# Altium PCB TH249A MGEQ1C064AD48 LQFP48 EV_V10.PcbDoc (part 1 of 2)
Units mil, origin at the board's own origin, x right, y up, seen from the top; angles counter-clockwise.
Board outline 3818.9 x 2637.8 mil, 2 copper layers (Top Layer, Bottom Layer); 103 components, 120 nets, 468 pads, 229 vias.
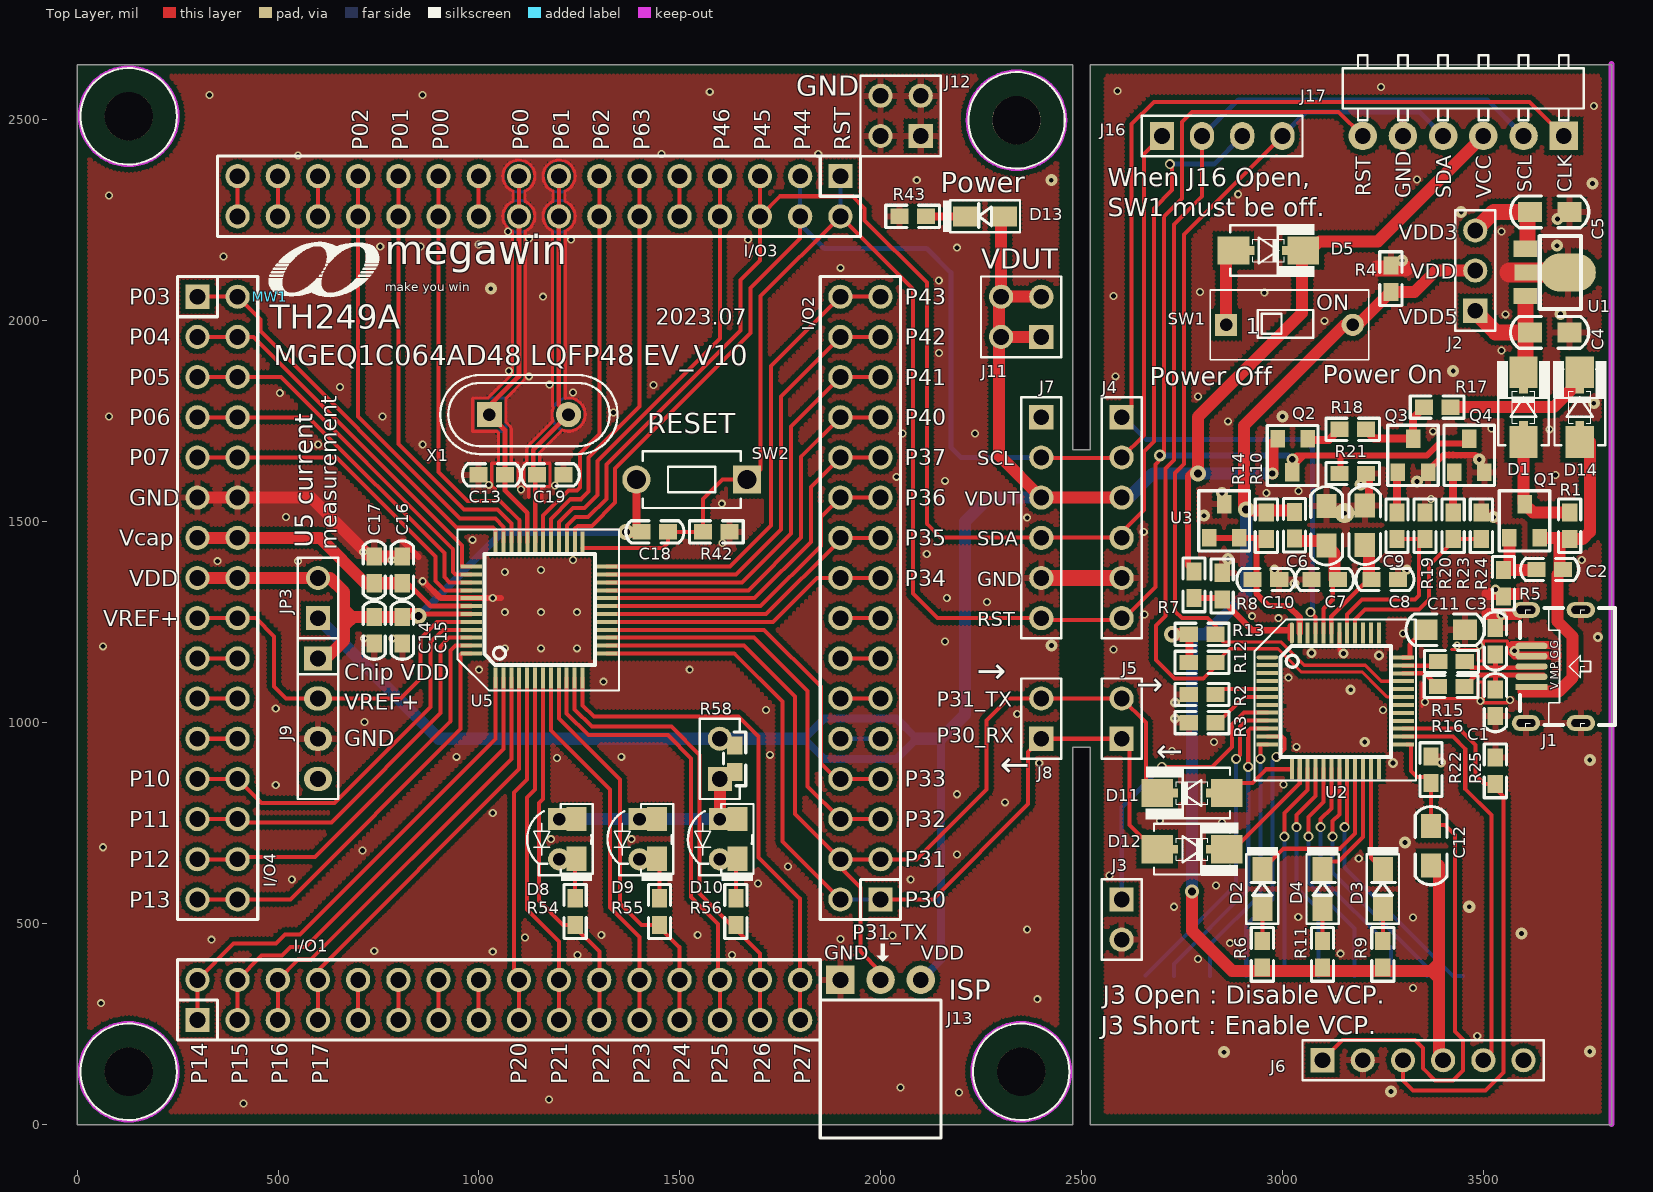
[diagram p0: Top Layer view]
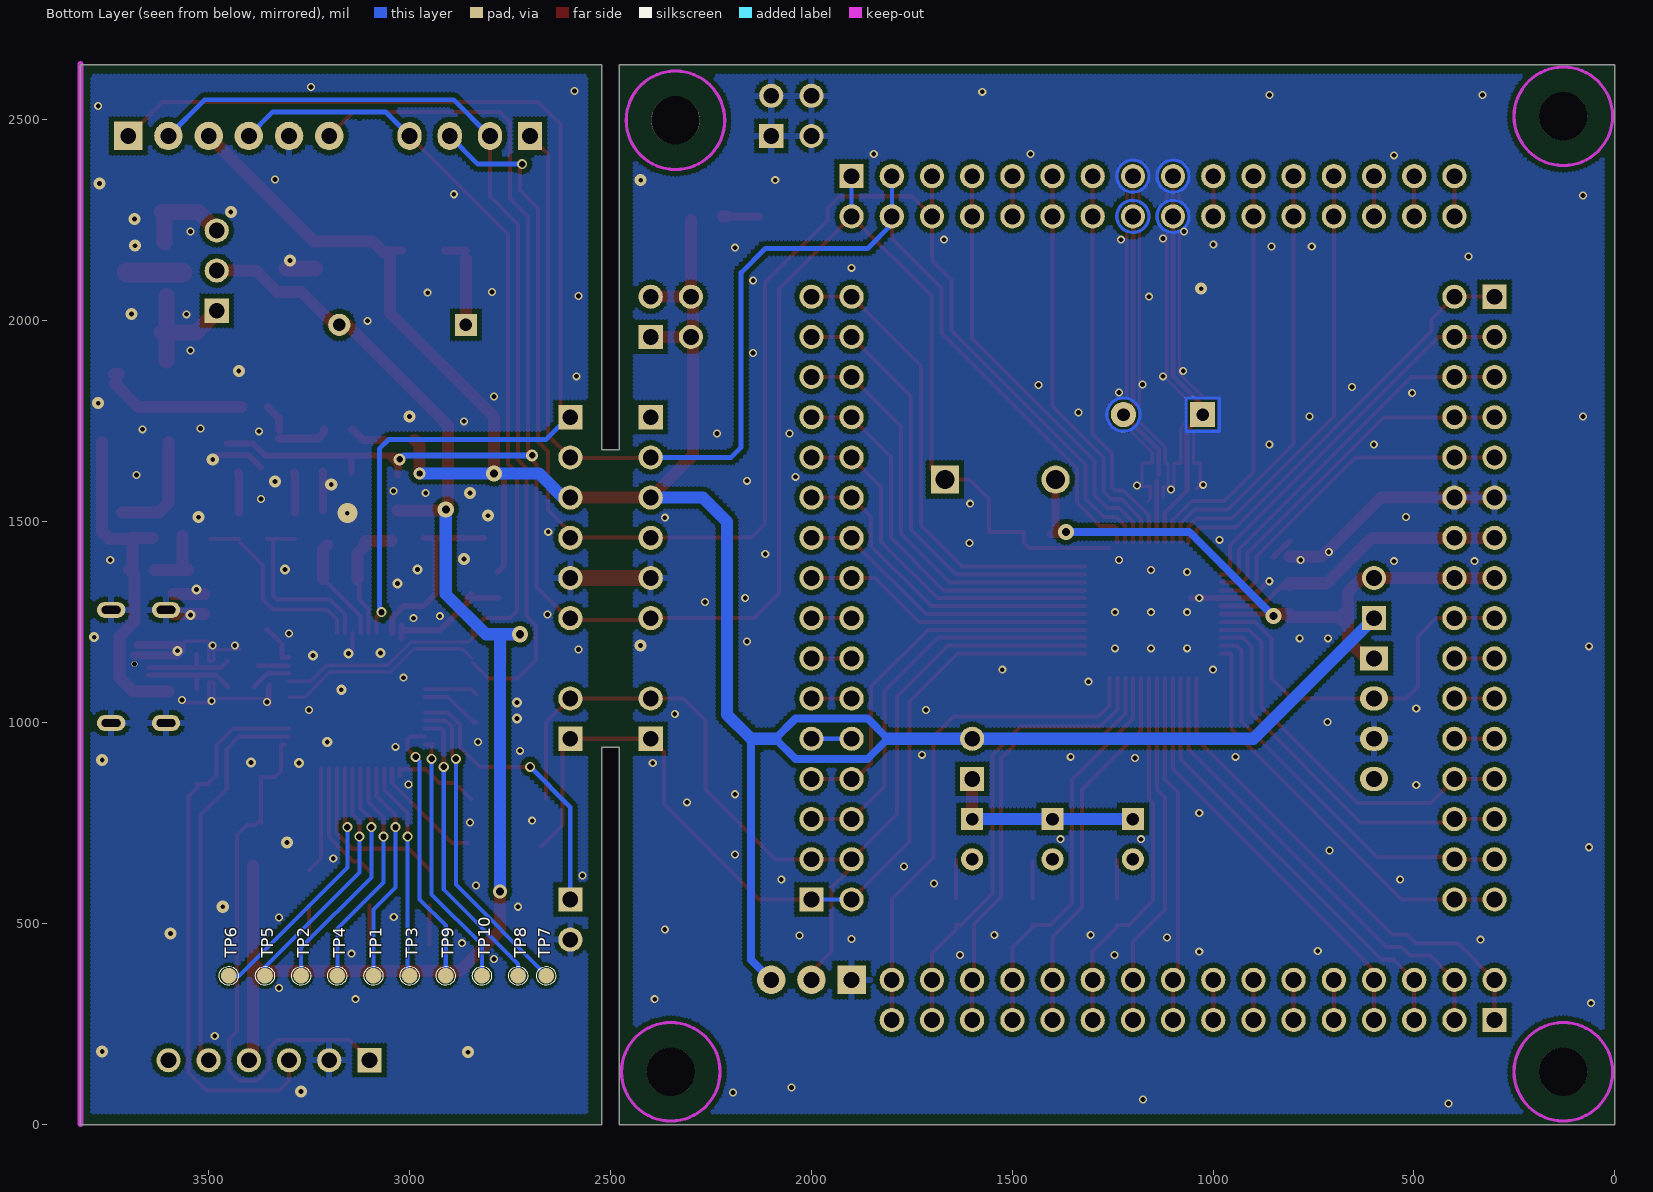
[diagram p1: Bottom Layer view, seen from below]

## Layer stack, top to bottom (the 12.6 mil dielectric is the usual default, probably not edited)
Top Layer: signal copper 1.4
Dielectric: dielectric 12.6, FR-4, Dk 4.8
Bottom Layer: signal copper 1.4

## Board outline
0,0 0,2637.8 2477.8,2637.8 2477.8,1678.74 2521.1,1678.74 2521.1,2637.8 3818.9,2637.8 3818.9,0 2521.1,0 2521.1,938.74 2477.8,938.74 2477.8,0

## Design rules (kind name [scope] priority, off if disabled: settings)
Clearance 12 [All] p1 off: gap=12
Clearance 7 [All] p2 off: gap=7
Clearance 6 [All] p3: gap=6
HoleSize 500-HoleSize [All] p1: absolutevalues=TRUE maxlimit=1500 minlimit=1 maxpercent=80.000 minpercent=20.000
PolygonConnect VIA [ISVIA] p1: connectstyle=Direct reliefconductorwidth=10 reliefentries=4 polygonreliefangle="90 Angle"
PolygonConnect "15 PolygonConnect" [All] p2: connectstyle=Relief reliefconductorwidth=15 reliefentries=4 polygonreliefangle="90 Angle"
RoomDefinition "2_MGEQ1C064AD48_LQFP48 EV_V10" [InComponentClass('2_MGEQ1C064AD48_LQFP48 EV_V10')] p1: confinementstyle=ConfineIn formatcopy=TRUE lockcomponents=FALSE outline -205.55,-40 3859.45,-40 3859.45,2680 -205.55,2680
RoomDefinition 1_MLink_V11 [InComponentClass('1_MLink_V11')] p2: confinementstyle=ConfineIn formatcopy=TRUE lockcomponents=FALSE outline -130.55,-90 3844.45,-90 3844.45,2735 -130.55,2735
RoutingVias [All] p1: holewidth=16 width=28 viastyle="Through Hole" minholewidth=16 minwidth=25 maxholewidth=28 maxwidth=50
ShortCircuit [All] p1 off: allowed=FALSE
SilkscreenOverComponentPads [All] p1: minsilkscreentomaskgap=10
SolderMaskExpansion [All] p1: expansion=4
UnRoutedNet [All] p1 off:
Width [All] p1: maxlimit=100 minlimit=6 preferedwidth=10
24 further rules are at their usual default settings.

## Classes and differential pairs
component class 1_MLink_V11: C1 C2 C3 C4 C5 C6 C7 C8 C9 C10 C11 C12 D1 D2 D3 D4 D5 D11 D12 D14 J1 J2 J3 J4 J5 J6 J16 J17 MW1 Q1 Q2 Q3 Q4 R1 R2 R3 R4 R5 R6 R7 R8 R9 R10 R11 R12 R13 R14 R15 R16 R17 R18 R19 R20 R21 R22 R23 R24 R25 SW1 TP1 TP2 TP3 TP4 TP5 TP6 TP7 TP8 TP9 TP10 U1 U2 U3
component class "2_MGEQ1C064AD48_LQFP48 EV_V10": C13 C14 C15 C16 C17 C18 C19 D8 D9 D10 D13 I/O1 I/O2 I/O3 I/O4 J7 J8 J9 J11 J12 J13 JP3 JP4 R42 R43 R54 R55 R56 R58 SW2 U5 X1

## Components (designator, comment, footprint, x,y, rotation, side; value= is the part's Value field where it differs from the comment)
C1 "15pF" 0603C#1 3529.45,1050 r90 top
C2 "0.1uF" 0603C#1 3664.41,1381.26 r0 top
C3 "15pF" 0603C#1 3529.45,1203 r270 top
C4 "4.7uF" 0805C 3664.41,1971.26 r0 top
C5 "4.7uF" 0805C 3664.41,2271.26 r0 top
C6 "4.7uF" 0805C 3109.41,1490 r90 top
C7 "0.1uF" 0603C#1 3104.45,1356.26 r180 top
C8 "0.1uF" 0603C#1 3254.45,1356.26 r0 top
C9 "4.7uF" 0805C 3204.41,1491.26 r90 top
C10 "0.1uF" 0603C#1 2958.5,1356.26 r180 top
C11 "4.7uF" 0805C 3404.41,1231.26 r0 top
C12 "4.7uF" 0805C 3369.45,694 r90 top
C13 "NC" 0603C#1 1031.49,1616.68 r0 top (schematic designator C18)
C14 "10uF" 0603C#2 739.45,1230 r270 top
C15 "0.1uF" 0603C#2 809.45,1230 r270 top
C16 "0.1uF" 0603C#2 809.45,1380 r90 top
C17 "4.7uF" 0603C#2 739.45,1380 r90 top
C18 "4.7uF" 0603C#2 1437.93,1475 r0 top (schematic designator C13)
C19 "NC" 0603C#1 1177.49,1616.68 r180 top
D1 "1N5817" DIODE_SMA_SOD323 3599.41,1785 r90 top
D2 "Yellow" 0805D 2949.45,586.26 r90 top
D3 "Green" 0805D 3249.45,586.26 r90 top
D4 "Red" 0805D 3099.45,586.26 r90 top
D5 "1N5817" DIODE_SMA_SOD323 2964.41,2175 r0 top
D8 "Red" LED38+0805 1199.45,710 r270 top
D9 "Yellow" LED38+0805 1399.45,710 r270 top
D10 "Green" LED38+0805 1599.45,710 r270 top
D11 "1N5817" DIODE_SMA_SOD323 2774.45,825 r180 top
D12 "1N5817" DIODE_SMA_SOD323 2774.45,685 r0 top
D13 "Yellow" 0805D 2259.45,2260 r180 top
D14 "1N5817" DIODE_SMA_SOD323 3739.41,1785 r90 top
I/O1 "CON16X2" PS16X2P254 299.45,260 r0 top locked
I/O2 "CON16X2" PS16X2P254 1999.45,560 r90 top locked
I/O3 "CON16X2" PS16X2P254 1899.45,2360 r180 top locked
I/O4 "CON16X2" PS16X2P254 299.45,2060 r270 top locked
J1 "MICRO_USB" USB_MICRO_7.X6P065 3742.21,1139.85 r90 top
J2 "2&3 (0 ohm)" PS3P254 3479.45,2025 r90 top
J3 "VCP Option" PS2P254 2599.45,560 r270 top locked
J4 "OnBoard ICP/SWD Connector" PS6P254 2599.45,1760 r270 top locked
J5 "NC" PS2P254 2599.45,960 r90 top locked
J6 "CON6" PS6P254 3099.45,160 r0 top locked
J7 "CON6" PS6P254 2399.45,1760 r270 top locked
J8 "NC" PS2P254 2399.45,960 r90 top
J9 "" PS4P254 599.45,1160 r270 top
J11 "VDUT" PS2X2P254 2399.45,1960 r90 top
J12 "GND" PS2X2P254 2099.45,2460 r90 top
J13 "3P2.54_F_90" PS3P254f_90 1899.45,360 r0 top
J16 "When J16 Open, SW1 must be off." PS4P254 2699.45,2460 r0 top locked
J17 "Off Board ICP/SWD Connector" PS6P254_90 3699.45,2460 r180 top locked
JP3 "JUMPER_2" ps2p254 599.45,1260 r90 top
MW1 "MW-A4" MEGAWIN_3.4 479.45,2060 r0 top
Q1 "IRLML6402" SOT23 3601.95,1501.97 r0 top
Q2 "2N3906" SOT23 3024.91,1665 r180 top
Q3 "3904" SOT23_132 3324.45,1665 r0 top
Q4 "3904" SOT23_132 3464.45,1665 r0 top
R1 "NC" 0603R 3714.45,1490 r270 top
R2 "0" 0603R 2799.45,1070 r0 top
R3 "NC" 0603R 2799.45,1000 r0 top
R4 "3.3K" 0603R 3269.45,2105 r270 top
R5 "1M" 0603R 3549.45,1347 r270 top
R6 "1K" 0603R 2949.45,423.26 r270 top
R7 "30K" 0603R 2779.45,1343 r90 top
R8 "10K" 0603R 2849.45,1340 r270 top
R9 "1K" 0603R 3249.45,423.26 r270 top
R10 "10" 0603R 3029.41,1491.26 r90 top
R11 "1K" 0603R 3099.45,423.26 r270 top
R12 "1.5K" 0603R 2799.45,1150 r180 top
R13 "1.5K" 0603R 2799.45,1220 r180 top
R14 "1K" 0603R 2959.41,1490 r270 top
R15 "30" 0603R 3420.29,1152.31 r180 top
R16 "30" 0603R 3419.45,1090 r180 top
R17 "4.7K" 0603R 3384.41,1785 r0 top
R18 "1K" 0603R 3174.45,1730 r0 top
R19 "4.7K" 0603R 3284.45,1490 r270 top
R20 "10K" 0603R 3354.45,1490 r270 top
R21 "1M" 0603R 3174.45,1620 r180 top
R22 "47K" 0603R 3369.45,883 r90 top
R23 "4.7K" 0603R 3424.45,1490 r270 top
R24 "10K" 0603R 3494.45,1490 r270 top
R25 "47K" 0603R 3529.45,880 r270 top
R42 "47K" 0603R 1590.93,1475 r180 top (schematic designator R27)
R43 "1K" 0603R 2079.45,2260 r180 top
R54 "470" 0603R 1239.45,530 r270 top
R55 "470" 0603R 1449.45,530 r270 top
R56 "470" 0603R 1639.45,530 r270 top
R58 "0" PS2p254+0603 1599.45,860 r90 top
SW1 "SW KEY-SPST" DIP2_SW 2859.49,1990 r0 top
SW2 "SW TACT-SPST" SW_T_2P 1529.45,1605 r180 top
TP1 "T POINT A" PIN1_1H0 3089.45,370 r90 bottom
TP2 "T POINT A" PIN1_1H0 3269.45,370 r90 bottom
TP3 "T POINT A" PIN1_1H0 2999.45,370 r180 bottom
TP4 "T POINT A" PIN1_1H0 3179.45,370 r180 bottom
TP5 "T POINT A" PIN1_1H0 3359.45,370 r180 bottom
TP6 "T POINT A" PIN1_1H0 3449.45,370 r180 bottom
TP7 "T POINT A" PIN1_1H0 2659.45,370 r180 bottom
TP8 "T POINT A" PIN1_1H0 2729.45,370 r180 bottom
TP9 "T POINT A" PIN1_1H0 2909.45,370 r180 bottom
TP10 "T POINT A" PIN1_1H0 2819.45,370 r90 bottom
U1 "AIC1734-33(SOT-89)" SOT89 3604.41,2120.31 r270 top
U2 "MG84FG516_LQFP48" LQFP48_7X7_050#1 3130.92,1054.39 r270 top
U3 "TL431A" SOT23 2854.41,1501.97 r0 top
U5 "MGEQ1C064AD48_LQFP48" LQFP48_7X7_050#2 1149.45,1280 r0 top locked
X1 "NC" X49U 1124.49,1766.68 r0 top

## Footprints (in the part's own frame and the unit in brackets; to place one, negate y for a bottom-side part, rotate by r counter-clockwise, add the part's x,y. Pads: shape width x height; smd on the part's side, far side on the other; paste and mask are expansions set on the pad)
0603C#1 [mil]
  rect 45x38 smd: 1(33,0) 2(-33,0)
  silkscreen extent -72,-28 72,28
0603C#2 [mil]
  rect 45x38 smd: 1(-33,0) 2(33,0)
  silkscreen extent -72,-28 72,28
0603R [mil]
  rect 45x38 smd: 1(33,0) 2(-33,0)
  silkscreen extent -67,-28 67,28
0805C [mil]
  rect 60x50 smd: 1(-49.21,0) 2(49.21,0)
  silkscreen extent -97,-39 97,39
0805D [mil]
  rect 60x50 smd: 1(-49.21,0) 2(49.21,0)
  silkscreen extent -87,-40 104,40
DIODE_SMA_SOD323 [mm]
  rect 2x1.8 smd: 1(-2.2,0) 2(2.2,0)
  rect 0.95x0.54 smd: 1(-1.35,0) 2(1.35,0)
  silkscreen extent -2.4,-1.68 2.92,1.68
DIP2_SW [mm]
  rect 1.4x1.4 hole 0.8: 1(0,0)
  round 1.4 hole 0.8: 2(8,0)
  silkscreen extent -1.02,-2.2 9.02,2.2
LED38+0805 [mm]
  rect 1.4x1.4 hole 0.8: 1(-1.27,0)
  rect 1.524x1.27 smd: 1(-1.267,1.11) 2(1.233,1.11)
  round 1.4 hole 0.8: 2(1.27,0)
  silkscreen extent -2.23,-2.02 2.64,2.13
LQFP48_7X7_050#1 [mm]
  oval 0.254x1.35 smd: 1(-2.75,-4.292)
  rect 0.254x1.35 smd: 2(-2.25,-4.292) 3(-1.75,-4.292) 4(-1.25,-4.292) 5(-0.75,-4.292) 6(-0.25,-4.292) 7(0.25,-4.292) 8(0.75,-4.292) 9(1.25,-4.292) 10(1.75,-4.292) 11(2.25,-4.292) 12(2.75,-4.292) 25(2.763,4.292) 26(2.263,4.292) 27(1.763,4.292) 28(1.263,4.292) 29(0.763,4.292) 30(0.263,4.292) 31(-0.237,4.292) 32(-0.737,4.292) 33(-1.237,4.292) 34(-1.737,4.292) 35(-2.237,4.292) 36(-2.737,4.292)
  rect 1.35x0.254 smd: 13(4.286,-2.744) 14(4.286,-2.244) 15(4.286,-1.744) 16(4.286,-1.244) 17(4.286,-0.744) 18(4.286,-0.244) 19(4.286,0.256) 20(4.286,0.756) 21(4.286,1.256) 22(4.286,1.756) 23(4.286,2.256) 24(4.286,2.756) 37(-4.286,2.756) 38(-4.286,2.256) 39(-4.286,1.756) 40(-4.286,1.256) 41(-4.286,0.756) 42(-4.286,0.256) 43(-4.286,-0.244) 44(-4.286,-0.744) 45(-4.286,-1.244) 46(-4.286,-1.744) 47(-4.286,-2.244)
  oval 1.35x0.254 smd: 48(-4.286,-2.744)
  silkscreen extent -5.15,-5.09 5.05,5.11
LQFP48_7X7_050#2 [mm]
  rect 0.254x1.35 smd: 1(-2.75,-4.292) 2(-2.25,-4.292) 3(-1.75,-4.292) 4(-1.25,-4.292) 5(-0.75,-4.292) 6(-0.25,-4.292) 7(0.25,-4.292) 8(0.75,-4.292) 9(1.25,-4.292) 10(1.75,-4.292) 11(2.25,-4.292) 12(2.75,-4.292) 25(2.763,4.292) 26(2.263,4.292) 27(1.763,4.292) 28(1.263,4.292) 29(0.763,4.292) 30(0.263,4.292) 31(-0.237,4.292) 32(-0.737,4.292) 33(-1.237,4.292) 34(-1.737,4.292) 35(-2.237,4.292) 36(-2.737,4.292)
  rect 1.35x0.254 smd: 13(4.286,-2.744) 14(4.286,-2.244) 15(4.286,-1.744) 16(4.286,-1.244) 17(4.286,-0.744) 18(4.286,-0.244) 19(4.286,0.256) 20(4.286,0.756) 21(4.286,1.256) 22(4.286,1.756) 23(4.286,2.256) 24(4.286,2.756) 37(-4.286,2.756) 38(-4.286,2.256) 39(-4.286,1.756) 40(-4.286,1.256) 41(-4.286,0.756) 42(-4.286,0.256) 43(-4.286,-0.244) 44(-4.286,-0.744) 45(-4.286,-1.244) 46(-4.286,-1.744) 47(-4.286,-2.244) 48(-4.286,-2.744)
  silkscreen extent -5.15,-5.09 5.05,5.11
MEGAWIN_3.4 [mil]
  silkscreen extent -2,0 272,135
PIN1_1H0 [mm]
  round 1 smd: 1(0,0)
  silkscreen extent -0.6,-0.6 0.6,0.6
PS2P254 [mil]
  rect 60x60 hole 39.37: 1(0,0)
  round 60 hole 39.37: 2(100,0)
  silkscreen extent -50,-50 150,50
ps2p254 [mil]
  rect 60x60 hole 39.37: 1(0,0)
  round 60 hole 39.37: 2(100,0)
  silkscreen extent -50,-50 150,50
PS2p254+0603 [mil]
  rect 60x60 hole 39.37: 1(0,0)
  rect 45x38 smd: 1(17,-36.85) 2(83,-36.85)
  round 60 hole 39.37: 2(100,0)
  silkscreen extent -50,-64 150,50
PS2X2P254 [mil]
  rect 60x60 hole 39.37: 1(0,0)
  round 60 hole 39.37: 2(0,100) 3(100,0) 4(100,100)
  silkscreen extent -50,-50 150,150
PS3P254 [mil]
  rect 60x60 hole 39.37: 1(0,0)
  round 60 hole 39.37: 2(100,0) 3(200,0)
  silkscreen extent -50,-50 250,50
PS3P254f_90 [mm]
  rect 1.8x1.8 hole 1: 1(0,0)
  round 1.8 hole 1: 2(2.54,0) 3(5.08,0)
  silkscreen extent -1.27,-10 6.35,-1.27
PS4P254 [mil]
  rect 60x70 hole 39.37: 1(0,0)
  oval 60x70 hole 39.37: 2(100,0) 3(200,0) 4(300,0)
  silkscreen extent -50,-50 350,50
PS6P254 [mil]
  rect 60x60 hole 39.37: 1(0,0)
  round 60 hole 39.37: 2(100,0) 3(200,0) 4(300,0) 5(400,0) 6(500,0)
  silkscreen extent -50,-50 550,50
PS6P254_90 [mm]
  rect 1.8x1.8 hole 1: 1(0,0)
  round 1.8 hole 1: 2(2.54,0) 3(5.08,0) 4(7.62,0) 5(10.16,0) 6(12.7,0)
  silkscreen extent -1.27,-5.11 13.97,-1
PS16X2P254 [mil]
  rect 60x60 hole 39.37: 1(0,0)
  round 60 hole 39.37: 2(0,100) 3(100,0) 4(100,100) 5(200,0) 6(200,100) 7(300,0) 8(300,100) 9(400,0) 10(400,100) 11(500,0) 12(500,100) 13(600,0) 14(600,100) 15(700,0) 16(700,100) 17(800,0) 18(800,100) 19(900,0) 20(900,100) 21(1000,0) 22(1000,100) 23(1100,0) 24(1100,100) 25(1200,0) 26(1200,100) 27(1300,0) 28(1300,100) 29(1400,0) 30(1400,100) 31(1500,0) 32(1500,100)
  silkscreen extent -50,-50 1550,150
SOT23 [mil]
  rect 36x43.31 smd: 1(-37.5,-41.97) 2(37.5,-41.97)
  rect 36x46.06 smd: 3(0.5,41.97)
  silkscreen extent -63,-74 63,75
SOT23_132 [mil]
  rect 36x43.31 smd: 1(-37.5,-41.97) 3(37.5,-41.97)
  rect 36x46.06 smd: 2(0.5,41.97)
  silkscreen extent -63,-74 63,75
SOT89 [mm]
  rect 1.016x1.5 smd: 1(-1.5,0) 3(1.5,0)
  oval 2.4x3.5 smd: 2(0,2.7)
  rect 1.016x2.6 smd: 2(0,0.6)
  silkscreen extent -2.3,0.9 2.3,3.5
SW_T_2P [mil]
  rect 70x70 hole 47.24: 1(-137.79,0)
  round 70 hole 47.24: 2(137.8,0)
  silkscreen extent -122,-71 122,71
USB_MICRO_7.X6P065 [mm] "J?"
  rect 0.4x2.032 smd: 1(-1.3,3.119)
  oval 0.4x2.032 smd: 2(-0.65,3.119) 3(0,3.119) 4(0.65,3.119) 5(1.3,3.119)
  oval 1x1.8 hole 0.5 slot 1.2 at 90 deg: 6(3.575,3.47) 7(3.575,0) 8(-3.575,0) 9(-3.575,3.47)
  silkscreen extent -3.83,-2.15 3.7,3.85
X49U [mm]
  rect 1.6x1.6 hole 0.8: 1(-2.5,0)
  round 1.6 hole 0.8: 2(2.5,0)
  silkscreen extent -5.6,-2.5 5.6,2.5

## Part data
C1 C3 C7 C12: library part "CAP NP_Dup1"
C2 C8 C10: library part "CAP NP"
C4 C5: library part "C NP"
C6 C9 C11: library part CAP
C13 C14 C15 C16 C17 C18 C19: library part CAP, "Capacitor"
D1 D5 D11 D12 D14: library part "DIODE SCHOTTKY"
D2 D3 D4: library part Led0_0
D8 D9 D10 D13: library part LED
J1: library part USB_Micro
J2 J13: library part CON3
J3 J5 J8: library part CON2
J4 J17: library part CON6
J7: library part CON6_Dup1
J9 J16: library part CON4
J11 J12: library part CON2X2
JP3: "Jumper"
MW1: library part MW_A4_2
Q1: library part "MOSFET P GSD"
Q2: library part 2N3906_0
Q3 Q4: library part "NPN BCE"
R1 R2 R3 R4: library part R_Dup4
R5 R6 R7 R8 R9 R11 R12 R13 R17 R18 R19 R22 R23 R25: library part R_Dup2
R10 R14 R15 R16: library part R_Dup5
R20 R21 R24: library part R_Dup1
R42: library part RES1
R43 R54 R55 R56 R58: library part R_Dup3
U1: library part AIC1722-33
U3: library part TL431/CYL
U5: library part IC48_FA245_MGEQ1C064AD48
X1: library part CRYSTAL

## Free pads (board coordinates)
  round 120 hole 120 unplated: 0(128.35,131.26) 0(128.35,2509.06) 0(2337.8,2499.06) 0(2349.45,131.26)

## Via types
v1: diameter 20, hole 12, Top Layer to Bottom Layer, tented both sides, 163 vias
v2: diameter 30, hole 12, Top Layer to Bottom Layer, tented both sides, 26 vias
v3: diameter 25, hole 12, Top Layer to Bottom Layer, tented both sides, 16 vias
v4: diameter 25, hole 16, Top Layer to Bottom Layer, tented both sides, 13 vias
v5: diameter 40, hole 20, Top Layer to Bottom Layer, tented both sides, 5 vias
v6: diameter 30, hole 16, Top Layer to Bottom Layer, tented both sides, 3 vias
v7: diameter 35, hole 20, Top Layer to Bottom Layer, tented both sides, 1 vias
v8: diameter 50, hole 12, Top Layer to Bottom Layer, tented both sides, 1 vias
v9: diameter 15, hole 12, Top Layer to Bottom Layer, tented both sides, 1 vias

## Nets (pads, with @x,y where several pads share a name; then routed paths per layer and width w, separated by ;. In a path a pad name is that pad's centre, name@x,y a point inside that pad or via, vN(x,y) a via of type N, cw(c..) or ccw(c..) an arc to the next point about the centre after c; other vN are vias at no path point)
2.495V: C10.1 R14.1 U2.47 U3.1 U3.2 | length 455.3
  Top Layer w15: U3.1@2814.41,1460 U3.1@2816.91,1460 U3.2@2891.91,1460 2934.41,1460 2934.41,1457 2934.41,1356.26 2934.41,1321.26 2965.67,1290 3014.45,1290 3042.59,1261.86 U2.47@3042.59,1223.13 ; 2939.41,1460 2959.41,1460 R14.1@2964.41,1460
516P24: TP7.1 U2.9 | length 790.4
  Top Layer w10: v4(2884.45,910) 2894.45,920 2894.45,990 2909.63,1005.18 U2.9@2961.93,1005.18
  Bottom Layer w10: TP7.1@2658.31,371.14 2884.45,597.28 v4(2884.45,910)
516P25: TP8.1 U2.10 | length 736.4
  Top Layer w10: v4(2914.45,890) 2914.45,980 2919.94,985.49 U2.10@2961.93,985.49
  Bottom Layer w10: TP8.1@2729.45,370 2729.45,399.85 2914.45,584.85 v4(2914.45,890)
516P26: TP9.1 U2.11 | length 674.3
  Top Layer w10: U2.11@2961.93,965.81 2998.64,965.81 3004.45,960 3004.45,935 v4(2984.45,915)
  Bottom Layer w10: TP9.1@2909.45,370 2909.45,495 2974.45,560 2974.45,905 v4(2984.45,915)
516P27: TP10.1 U2.12 | length 649.5
  Top Layer w10: v4(2944.45,910) 2944.45,943.23 2941.56,946.12 U2.12@2961.93,946.12
  Bottom Layer w10: TP10.1@2819.45,370 2819.45,447.43 2944.45,572.43 v4(2944.45,910)
516P32: TP3.1 U2.15 | length 762.5
  Top Layer w10: v4@3004.45,715 v4(3004.45,716.26) 3004.45,775 3062.27,832.82 U2.15@3062.27,885.65
  Bottom Layer w10: TP3.1@3004.45,375 3004.45,630 ; 3004.45,402.13 3004.45,630 ; v4@3004.45,715 3004.45,630
516P33: TP1.1 U2.16 | length 558.1
  Top Layer w10: v4(3034.45,740) 3034.45,770 3081.96,817.51 U2.16@3081.96,885.65
  Bottom Layer w10: v4(3034.45,740) 3034.45,590.15 3089.45,535.15 TP1.1@3089.45,370
516P34: TP4.1 U2.17 | length 578.7
  Top Layer w10: v4@3064.45,715 v4(3064.45,716.26) 3064.45,765 3101.64,802.19 U2.17@3101.64,885.65
  Bottom Layer w10: v4@3064.45,715 3064.45,602.57 3179.45,487.57 TP4.1@3179.45,370
516P35: TP2.1 U2.18 | length 599.3
  Top Layer w10: v4(3094.45,740) 3094.45,760 3121.33,786.88 U2.18@3121.33,885.65
  Bottom Layer w10: v4(3094.45,740) 3094.45,615 3269.45,440 TP2.1@3269.45,370
516P36: TP5.1 U2.19 | length 619.9
  Top Layer w10: v4@3124.45,715 v4(3124.45,716.26) 3124.45,755 3141.01,771.56 U2.19@3141.01,885.65
  Bottom Layer w10: v4@3124.45,715 3124.45,627.43 3359.45,392.43 TP5.1@3359.45,370
516P37: TP6.1 U2.20 | length 655.2
  Top Layer w10: v4(3154.45,740) 3160.7,746.25 U2.20@3160.7,885.65
  Bottom Layer w10: v4(3154.45,740) 3154.45,639.85 3424.3,370 TP6.1@3449.45,370
CHIP_VDD: C14.1 C15.1 C18.1 I/O4.15 I/O4.16 J9.1 JP3.2 SW2.2 U5.43 | length 1758
  Top Layer w12: v5@839.45,1270.41 848.88,1270.41 849.45,1270.41 U5.43@980.71,1270.41
  Top Layer w15: 669.23,1234.78 694.45,1260 ; 669.23,1288.22 694.45,1263
  Top Layer w20: v5@1365.93,1470 C18.1@1391.65,1470 ; SW2.2@1391.65,1605 1391.65,1475 C18.1@1391.65,1470 ; C18.1@1404.93,1470 C18.1@1391.65,1470
  Top Layer w30: I/O4.15@299.45,1360 I/O4.16@399.45,1360 JP3.2@599.45,1360 629.45,1360 664.45,1325 664.45,1263 ; J9.1@599.45,1160 620,1160 664.45,1204.45 664.45,1263 ; C15.1@809.45,1263 C14.1@739.45,1263 694.45,1263 664.45,1263 ; C15.1@809.45,1270.41 v5@848.88,1270.41
  Bottom Layer w20: v5(849.45,1265) 1059.45,1475 v5(1365.93,1475)
D+: C3.1 J1.3 R15.2 | length 231.2
  Top Layer w12: R15.2@3453.29,1152.31 3469.12,1136.47 3619.41,1136.47 J1.3@3649.45,1136.47 ; 3529.45,1141.47 C3.1@3529.45,1170
D-: C1.1 J1.2 R16.2 | length 239.3
  Top Layer w12: R16.2@3452.45,1090 3480.92,1118.47 3619.41,1118.47 J1.2@3649.45,1118.47 ; C1.1@3529.45,1083 3529.45,1113.47
DET_VDUT: R7.2 R8.1 U2.48 | length 318.6
  Top Layer w15: R7.2@2779.45,1310 2849.45,1310 R8.1@2857.01,1310 ; R8.1@2847.01,1320 R8.1@2854.73,1312.28 ; R8.1@2847.21,1307.24 2848.45,1306 2924.45,1230 3015.39,1230 ; U2.48@3019.45,1210 3019.45,1223.13 U2.48@3019.45,1240
DUT_CLK: J4.1 J17.1 U2.45 | length 2846.4
  Top Layer w10: J4.1@2599.45,1760 2624.45,1785 2624.45,2490 2679.45,2545 3614.45,2545 J17.1@3699.45,2460 ; v4(3069.33,1275) 3081.96,1262.37 U2.45@3081.96,1223.13
  Bottom Layer w12: J4.1@2599.45,1760 2604.45,1760 2659.45,1705 3050.67,1705 3074.41,1681.26 3074.41,1280.08 v4(3069.33,1275)
DUT_RST: C18.2 I/O3.1 I/O3.2 J4.6 J7.6 J17.6 Q2.3 Q4.2 R21.1 R42.1 SW2.1 U5.25 | length 5641.7
  Top Layer w10: U5.25@1258.22,1435 1458.49,1435 1470.93,1447.44 C18.2@1470.93,1475 R42.1@1557.93,1475 1557.93,1557 1605.93,1605 SW2.1@1667.24,1605 ; SW2.1@1667.24,1630 1700.93,1630 1700.93,2061.48 I/O3.2@1899.45,2260 2080.45,2079 2080.45,1320.9 2141.35,1260 J7.6@2399.45,1260 ; J7.6@2399.45,1255 J4.6@2599.45,1255 ; J4.6@2602.45,1257 2683.2,1337.75 2683.2,1642.75 2699.95,1659.5 2704.45,1664 2704.45,1665 2704.45,2260 2749.45,2305 2749.45,2495 2774.45,2520 3139.45,2520 J17.6@3199.45,2460
  Top Layer w15: Q2.3@3024.41,1635 Q2.3@3029.41,1640 ; v6(3024.41,1655) 3034.41,1665 3054.41,1665 ; Q2.3@3029.41,1615 3029.41,1623.03 Q2.3@3029.41,1640 ; v6@3029.41,1658 3029.41,1655 Q2.3@3029.41,1640 ; R21.1@3144.41,1622 3144.41,1665 ; Q4.2@3455.03,1695 3389.41,1695 3359.41,1665 3144.41,1665 ; Q2.3@3029.41,1640 3034.41,1645 3054.41,1665 ; 3054.41,1665 3144.41,1665
  Bottom Layer w10: I/O3.2@1899.45,2260 I/O3.1@1899.45,2360
  Bottom Layer w15: v6(2694.45,1665) 3014.41,1665 v6(3024.41,1655)
FAIL: D4.2 U2.22 | length 305.7
  Top Layer w10: D4.2@3099.45,631 3101.69,633.24 3123.45,655 3139.45,655 3200.07,715.62 U2.22@3200.07,885.65
ICP/SWD_SCL: J16.2 J17.2 R12.2 U2.31 | length 2959.9
  Top Layer w8: R12.2@2844.45,1160 2868.45,1184 2988.41,1184 3046.41,1126 3198.41,1126 3238.3,1086.1 ; 3238.35,1086.1 3260.72,1063.73 U2.31@3299.91,1063.73
  Top Layer w10: J16.2@2799.45,2485 J16.2@2799.45,2460 2799.45,2310 2729.45,2240 2729.45,1654 2708.2,1632.75 2708.2,1265.05 2684.41,1241.26 2684.41,1156.26 2730.67,1110 2802.45,1110 2837.45,1145 R12.2@2842.45,1150
  Bottom Layer w12: J16.2@2799.45,2460 2889.45,2550 3509.45,2550 J17.2@3599.45,2460
ICP/SWD_SDA: J16.4 J17.4 R13.2 U2.33 | length 2399.4
  Top Layer w8: R13.2@2832.45,1220 2851.45,1201 2995.45,1201 3053.45,1143 3205.45,1143 3245.35,1103.1 U2.33@3299.91,1103.1
  Top Layer w10: R13.2@2842.45,1220 2842.45,1231 2813.45,1260 2749.45,1260 2732.2,1277.25 2732.2,1621.75 2754.45,1644 2754.45,2215 J16.4@2999.45,2460
  Bottom Layer w12: J16.4@2999.45,2460 3059.45,2520 3339.45,2520 J17.4@3399.45,2460
MLINK_RXD: D11.2 I/O2.3 I/O2.4 J5.2 J8.2 J13.2 U5.14 | length 2565.4
  Top Layer w10: U5.14@1318.19,1191.67 1660.18,1191.67 1786.44,1065.4 1786.44,773.01 I/O2.4@1899.45,660 I/O2.3@1999.45,660 ; I/O2.4@1899.45,640 1909.45,630 ; I/O2.4@1909.45,650 1909.45,630 ; J13.2@1999.45,360 1999.45,380 1949.45,430 1949.45,590 1909.45,630 ; I/O2.3@1999.45,650 I/O2.3@1999.45,660 ; D11.2@2659.45,810 2659.45,825 2659.45,1000 J5.2@2599.45,1060 J8.2@2399.45,1060 2317.55,1060 2263.22,1005.67 2263.22,833.77 2089.45,660 I/O2.3@1999.45,660
MLINK_TXD: D12.1 I/O2.1 I/O2.2 J5.1 J8.1 U5.13 | length 2282
  Top Layer w10: U5.13@1318.19,1171.98 1635.32,1171.98 1754.95,1052.36 1754.95,704.5 I/O2.2@1899.45,560 I/O2.2@1899.45,565 ; I/O2.1@1999.45,560 2129.45,560 2366.78,797.33 2366.78,927.33 J8.1@2399.45,960 J5.1@2599.45,960 J5.1@2605.22,954.23 ; J5.1@2619.45,958 2619.45,745 D12.1@2672.83,691.61
  Bottom Layer w10: I/O2.2@1899.45,560 I/O2.1@1999.45,560
NetC2_2: C2.2 Q1.1 R5.2 | length 170
  Top Layer w30: R5.2@3549.45,1380 R5.2@3564.45,1380 ; Q1.1@3564.45,1465 Q1.1@3564.45,1460 R5.2@3564.45,1380 ; C2.2@3634.45,1380 3631.41,1380 R5.2@3564.45,1380
NetC6_1: C6.1 C7.2 R10.2 U2.44 | length 306.5
  Top Layer w11: U2.44@3101.64,1223.13 3101.64,1283.49 3124.41,1306.26 C7.2@3124.41,1351.26
  Top Layer w30: R10.2@3044.45,1452 3109.41,1452 C6.1@3109.41,1440.79 3129.41,1420.79 C7.2@3129.41,1356.26
NetC8_2: C8.2 C9.1 U2.43 | length 261.6
  Top Layer w11: U2.43@3121.33,1223.13 3121.33,1264.18 C8.2@3214.41,1357.26
  Top Layer w30: C9.1@3204.41,1442.05 3214.41,1432.05 C8.2@3214.41,1357.26
NetC11_1: C11.1 U2.36 | length 103.2
  Top Layer w12: U2.36@3299.91,1162.16 3316.61,1162.16 3316.61,1194.68 3353.83,1231.9 C11.1@3355.2,1231.9
NetD1_1: D1.1 Q1.3 R1.2 | length 276.4
  Top Layer w30: D1.1@3599.41,1698.39 3599.41,1546.98 Q1.3@3602.45,1543.94 3623.38,1523 R1.2@3714.45,1523
NetD2_1: D2.1 R6.2 | length 97
  Top Layer w10: R6.2@2949.45,448 R6.2@2949.45,456.26 D2.1@2949.45,537.05 D2.1@2949.45,545
NetD3_1: D3.1 R9.2 | length 97
  Top Layer w10: R9.2@3249.45,448 R9.2@3249.45,456.26 D3.1@3249.45,537.05 D3.1@3249.45,545
NetD4_1: D4.1 R11.2 | length 97
  Top Layer w10: R11.2@3099.45,448 R11.2@3099.45,456.26 D4.1@3099.45,537.05 D4.1@3099.45,545
NetD5_1: D5.1 SW1.1 | length 215.1
  Top Layer w20: D5.1@2860.28,2175 D5.1@2877.8,2175 D5.1@2911.26,2175
  Top Layer w30: SW1.1@2859.49,1990 D5.1@2859.49,2154.13
NetD8_1: D8.1 D9.1 D10.1 R58.1 | length 500
  Top Layer w30: D10.1@1599.45,760 R58.1@1599.45,860
  Bottom Layer w30: D8.1@1199.45,760 D9.1@1399.45,760 D10.1@1599.45,760
NetD8_2: D8.2 R54.2 | length 94.8
  Top Layer w10: R54.2@1239.45,563 D8.2@1239.45,657.76
NetD9_2: D9.2 R55.2 | length 92.1
  Top Layer w10: R55.2@1449.45,563 D9.2@1449.45,655.13
NetD10_2: D10.2 R56.2 | length 94.8
  Top Layer w10: R56.2@1639.45,563 D10.2@1639.45,657.76
NetD11_1: D11.1 U2.13 | length 209.6
  Top Layer w10: D11.1@2846.06,810 D11.1@2861.06,825 D11.1@2876.06,840 ; D11.1@2884.45,850 2924.45,850 2958.51,884.06 U2.13@3020.37,884.06 ; U2.13@3022.9,868.45 U2.13@3022.9,885.65
NetD12_2: D12.2 U2.14 | length 287
  Top Layer w10: D12.2@2854.45,700 2861.06,700 2894.45,700 3042.59,848.14 U2.14@3042.59,885.65
NetD13_2: D13.2 R43.2 | length 90
  Top Layer w20: R43.2@2129.45,2260 D13.2@2210.24,2260
  Top Layer w30: D13.2@2210.24,2260 D13.2@2219.45,2260
NetD14_2: D14.2 R17.1 | length 348.7
  Top Layer w30: R17.1@3417.41,1785 3669.41,1785 ; 3674.41,1785 D14.2@3733.48,1844.07 ; D14.2@3722.56,1868.15 D14.2@3734.41,1868.15 ; D14.2@3728.48,1844.07 D14.2@3729.41,1845
NetI/O1_9: I/O1.9 I/O1.10 | length 100
  Top Layer w10: I/O1.9@699.45,260 I/O1.10@699.45,360
NetI/O1_11: I/O1.11 I/O1.12 | length 100
  Top Layer w10: I/O1.11@799.45,260 I/O1.12@799.45,360
NetI/O1_13: I/O1.13 I/O1.14 | length 100
  Top Layer w10: I/O1.13@899.45,260 I/O1.14@899.45,360
NetI/O1_15: I/O1.15 I/O1.16 | length 100
  Top Layer w10: I/O1.15@999.45,260 I/O1.16@999.45,360
NetI/O2_9: I/O2.9 I/O2.10 | length 100
  Bottom Layer w10: I/O2.10@1899.45,960 I/O2.9@1999.45,960
NetI/O2_11: I/O2.11 I/O2.12 | length 100
  Top Layer w10: I/O2.12@1899.45,1060 I/O2.11@1999.45,1060
NetI/O2_13: I/O2.13 I/O2.14 | length 100
  Top Layer w10: I/O2.14@1899.45,1160 I/O2.13@1999.45,1160
NetI/O2_15: I/O2.15 I/O2.16 | length 100
  Top Layer w10: I/O2.16@1899.45,1260 I/O2.15@1999.45,1260
NetI/O3_9: I/O3.9 I/O3.10 | length 100
  Top Layer w10: I/O3.10@1499.45,2260 I/O3.9@1499.45,2360
NetI/O3_19: I/O3.19 I/O3.20 | length 100
  Top Layer w10: I/O3.20@999.45,2260 I/O3.19@999.45,2360
NetI/O3_27: I/O3.27 I/O3.28 | length 100
  Top Layer w10: I/O3.28@599.45,2260 I/O3.27@599.45,2360
NetI/O3_29: I/O3.29 I/O3.30 | length 100
  Top Layer w10: I/O3.30@499.45,2260 I/O3.29@499.45,2360
NetI/O3_31: I/O3.31 I/O3.32 | length 100
  Top Layer w10: I/O3.32@399.45,2260 I/O3.31@399.45,2360
NetI/O4_19: I/O4.19 I/O4.20 | length 100
  Top Layer w10: I/O4.19@299.45,1160 I/O4.20@399.45,1160
NetI/O4_21: I/O4.21 I/O4.22 | length 100
  Top Layer w10: I/O4.21@299.45,1060 I/O4.22@399.45,1060
NetI/O4_23: I/O4.23 I/O4.24 | length 100
  Top Layer w10: I/O4.23@299.45,960 I/O4.24@399.45,960
NetQ2_1: Q2.1 R18.2 | length 89.8
  Top Layer w20: Q2.1@3062.41,1703.94 3115.38,1703.94 R18.2@3141.45,1730
NetQ3_1: Q3.1 R19.2 | length 117.1
  Top Layer w20: R19.2@3284.45,1540.04 R19.2@3284.45,1523 Q3.1@3284.45,1620.53 ; Q3.1@3286.95,1620.53 Q3.1@3286.95,1623.03
NetQ3_2: Q3.2 R17.2 R18.1 | length 192.7
  Top Layer w20: R18.1@3212.45,1730 3212.45,1721.96 3227.44,1706.97 Q3.2@3324.95,1706.97 ; 3324.95,1730 3324.95,1758.54 R17.2@3351.41,1785
NetQ4_1: Q4.1 R23.2 | length 100
  Top Layer w20: R23.2@3424.45,1523 Q4.1@3424.45,1620.53 ; Q4.1@3426.95,1620.53 Q4.1@3426.95,1623.03
NetR15_1: R15.1 U2.35 | length 108.8
  Top Layer w12: U2.35@3299.91,1141.47 3329.45,1141.47 ; 3361.71,1141.47 3329.45,1141.47 ; R15.1@3376.45,1141.47 3329.45,1141.47
NetR16_1: R16.1 U2.34 | length 100.1
  Top Layer w12: U2.34@3299.91,1122.79 3353.66,1122.79 R16.1@3386.45,1090
OCD_CLK/P44: I/O3.3 I/O3.4 J4.2 J7.2 J16.1 U5.26 | length 3341.5
  Top Layer w10: U5.26@1238.53,1448.99 1238.53,1482.6 1245.93,1490 1280.93,1490 1338.93,1548 1338.93,1633 1675.93,1970 1675.93,2081.48 1799.45,2205 I/O3.4@1799.45,2260 ; J7.2@2399.45,1659 J4.2@2599.45,1659 ; J4.2@2599.45,1660 2654.45,1715 2654.45,2415 J16.1@2699.45,2460
  Bottom Layer w10: I/O3.4@1799.45,2240 I/O3.4@1799.45,2260 I/O3.3@1799.45,2360
  Bottom Layer w12: I/O3.4@1799.45,2240 1859.45,2180 2114.45,2180 2174.45,2120 2174.45,1685 2199.45,1660 J7.2@2399.45,1660 J7.2@2384.45,1675
OCD_SDA/P45: I/O3.5 I/O3.6 J4.4 J7.4 J16.3 U5.27 | length 3943.2
  Top Layer w10: U5.27@1218.85,1448.99 1218.85,1490.75 1240.09,1512 1271.82,1512 1316.93,1557.11 1316.93,1642.11 1650.93,1976.11 1650.93,2101.48 1699.45,2150 I/O3.6@1699.45,2260 ; I/O3.5@1699.45,2360 I/O3.6@1699.45,2260 ; J7.4@2399.45,1460 2398.45,1461 2148.45,1461 2114.45,1495 2114.45,2095 1959.45,2250 1959.45,2280 1929.45,2310 1749.45,2310 I/O3.6@1699.45,2260 ; J7.4@2399.45,1461 J4.4@2585.45,1461 ; J4.4@2592.45,1467 2654.45,1529 2654.45,1675 2679.45,1700 2679.45,2280 2724.45,2325 v4@2724.45,2390
  Bottom Layer w12: v4(2719.45,2390) 2829.45,2390 J16.3@2899.45,2460
P00: I/O3.21 I/O3.22 U5.33 | length 1041.8
  Top Layer w10: I/O3.21@899.45,2360 I/O3.22@899.45,2260 899.45,1624.14 971.59,1552 1052.45,1552 1100.74,1503.71 U5.33@1100.74,1448.99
